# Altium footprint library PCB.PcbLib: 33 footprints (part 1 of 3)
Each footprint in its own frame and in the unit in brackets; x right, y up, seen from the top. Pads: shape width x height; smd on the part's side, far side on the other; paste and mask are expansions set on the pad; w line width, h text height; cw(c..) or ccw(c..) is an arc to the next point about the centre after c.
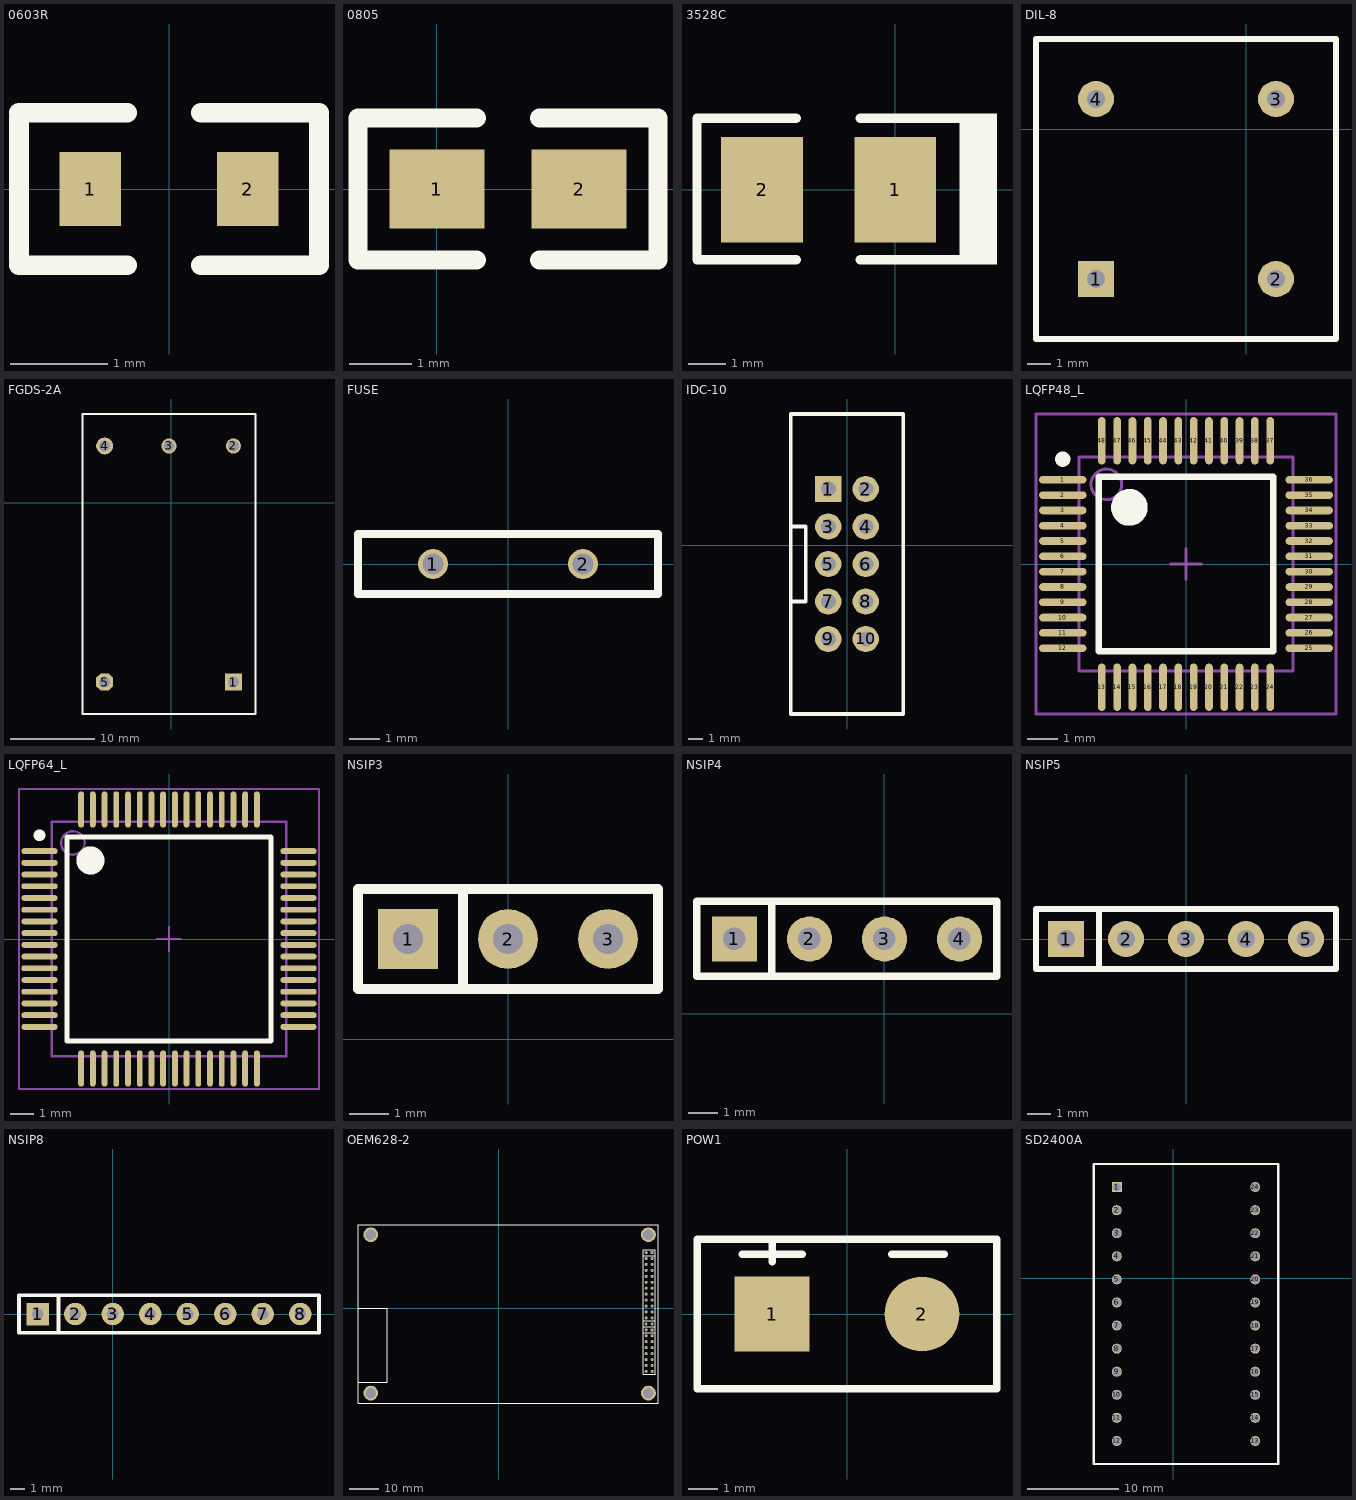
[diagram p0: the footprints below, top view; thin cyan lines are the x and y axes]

## 0603R [mil]
height 62.99
pads (2):
  rect 25x30 smd: 1(-32,0) 2(32,0)
Top Overlay:
  lines w8: -61,-31 -17,-31 ; -61,-29 -61,29 ; -61,31 -17,31 ; 13,-31 61,-31 ; 13,31 61,31 ; 61,-29 61,29

## 0805 [mil]
pads (2):
  rect 60x50 smd: 1(0,0) 2(90,0)
Top Overlay:
  lines w12: 25,-45 -50,-45 -50,45 25,45 ; 65,-45 140,-45 140,45 65,45

## 3528C [mm]
pads (2):
  rect 2.2x2.85 smd: 1(0,0) 2(-3.581,0)
Top Overlay:
  rectangle: 1.727,-2.014 2.743,2.058
  lines w0.254: -2.667,-1.88 -5.334,-1.88 -5.334,1.93 -2.667,1.93 ; -0.94,-1.88 1.727,-1.88 ; -0.94,1.93 1.727,1.93

## DIL-8 [mil]
pads (4):
  rect 60x60 hole 30: 1(-250,-250)
  round 60 hole 30: 2(50,-250) 3(50,50) 4(-250,50)
Top Overlay:
  lines w10: -350,-350 150,-350 150,150 -350,150 -350,-350

## FGDS-2A [mm]
height 1.6
pads (5):
  rect 2x2 hole 1.3: 1(7.37,-21.22)
  round 1.8 hole 1.3: 2(7.37,6.72) 3(-0.25,6.72)
  round 2 hole 1.3: 4(-7.87,6.72)
  oct 2x2 hole 1.3: 5(-7.87,-21.22)
Top Overlay:
  lines w0.254: -10.5,-25 -10.5,10.5 10,10.5 10,-25 -10.5,-25

## FUSE [mm]
height 1.6
pads (2):
  round 1 hole 0.7: 1(-2.5,0) 2(2.5,0)
Top Overlay:
  lines w0.254: -5,-1 5,-1 5,1 -5,1 -5,-1

## IDC-10 [mil] "XZZ"
pads (10):
  rect 70x70 hole 40: 1(-50,150)
  round 70 hole 40: 2(50,150) 3(-50,50) 4(50,50) 5(-50,-50) 6(50,-50) 7(-50,-150) 8(50,-150) 9(-50,-250) 10(50,-250)
Top Overlay:
  lines w10: -150,-150 -110,-150 -110,50 -150,50 ; -150,-450 -150,350 150,350 150,-450 -150,-450

## LQFP48_L [mm]
height 1.6
pads (48):
  oval 1.55x0.25 smd: 1(-4.025,2.75) 2(-4.025,2.25) 3(-4.025,1.75) 4(-4.025,1.25) 5(-4.025,0.75) 6(-4.025,0.25) 7(-4.025,-0.25) 8(-4.025,-0.75) 9(-4.025,-1.25) 10(-4.025,-1.75) 11(-4.025,-2.25) 12(-4.025,-2.75) 25(4.025,-2.75) 26(4.025,-2.25) 27(4.025,-1.75) 28(4.025,-1.25) 29(4.025,-0.75) 30(4.025,-0.25) 31(4.025,0.25) 32(4.025,0.75) 33(4.025,1.25) 34(4.025,1.75) 35(4.025,2.25) 36(4.025,2.75)
  oval 0.25x1.55 smd: 13(-2.75,-4.025) 14(-2.25,-4.025) 15(-1.75,-4.025) 16(-1.25,-4.025) 17(-0.75,-4.025) 18(-0.25,-4.025) 19(0.25,-4.025) 20(0.75,-4.025) 21(1.25,-4.025) 22(1.75,-4.025) 23(2.25,-4.025) 24(2.75,-4.025) 37(2.75,4.025) 38(2.25,4.025) 39(1.75,4.025) 40(1.25,4.025) 41(0.75,4.025) 42(0.25,4.025) 43(-0.25,4.025) 44(-0.75,4.025) 45(-1.25,4.025) 46(-1.75,4.025) 47(-2.25,4.025) 48(-2.75,4.025)
Top Overlay:
  circle w0.25: c-4.025,3.425 r0.125
  circle w0.6: c-1.85,1.85 r0.3
  lines w0.2: -2.85,-2.85 -2.85,2.85 2.85,2.85 2.85,-2.85 -2.85,-2.85
Mechanical 13:
  circle w0.1: c-2.6,2.6 r0.5
  lines w0.1: -3.5,-3.5 -3.5,3.5 3.5,3.5 3.5,-3.5 -3.5,-3.5
Mechanical 15:
  lines w0.1: -0.5,0 0.5,0 ; 0,-0.5 0,0.5 ; -4.9,-4.9 -4.9,4.9 4.9,4.9 4.9,-4.9 -4.9,-4.9

## LQFP64_L [mm]
pads (64):
  oval 1.55x0.25 smd: 1(-5.525,3.75) 2(-5.525,3.25) 3(-5.525,2.75) 4(-5.525,2.25) 5(-5.525,1.75) 6(-5.525,1.25) 7(-5.525,0.75) 8(-5.525,0.25) 9(-5.525,-0.25) 10(-5.525,-0.75) 11(-5.525,-1.25) 12(-5.525,-1.75) 13(-5.525,-2.25) 14(-5.525,-2.75) 15(-5.525,-3.25) 16(-5.525,-3.75) 33(5.525,-3.75) 34(5.525,-3.25) 35(5.525,-2.75) 36(5.525,-2.25) 37(5.525,-1.75) 38(5.525,-1.25) 39(5.525,-0.75) 40(5.525,-0.25) 41(5.525,0.25) 42(5.525,0.75) 43(5.525,1.25) 44(5.525,1.75) 45(5.525,2.25) 46(5.525,2.75) 47(5.525,3.25) 48(5.525,3.75)
  oval 0.25x1.55 smd: 17(-3.75,-5.525) 18(-3.25,-5.525) 19(-2.75,-5.525) 20(-2.25,-5.525) 21(-1.75,-5.525) 22(-1.25,-5.525) 23(-0.75,-5.525) 24(-0.25,-5.525) 25(0.25,-5.525) 26(0.75,-5.525) 27(1.25,-5.525) 28(1.75,-5.525) 29(2.25,-5.525) 30(2.75,-5.525) 31(3.25,-5.525) 32(3.75,-5.525) 49(3.75,5.525) 50(3.25,5.525) 51(2.75,5.525) 52(2.25,5.525) 53(1.75,5.525) 54(1.25,5.525) 55(0.75,5.525) 56(0.25,5.525) 57(-0.25,5.525) 58(-0.75,5.525) 59(-1.25,5.525) 60(-1.75,5.525) 61(-2.25,5.525) 62(-2.75,5.525) 63(-3.25,5.525) 64(-3.75,5.525)
Top Overlay:
  circle w0.25: c-5.525,4.425 r0.125
  circle w0.6: c-3.35,3.35 r0.3
  lines w0.2: -4.35,-4.35 -4.35,4.35 4.35,4.35 4.35,-4.35 -4.35,-4.35
Mechanical 13:
  circle w0.1: c-4.1,4.1 r0.5
  lines w0.1: -5,-5 -5,5 5,5 5,-5 -5,-5
Mechanical 15:
  lines w0.1: -0.5,0 0.5,0 ; 0,-0.5 0,0.5 ; -6.4,-6.4 -6.4,6.4 6.4,6.4 6.4,-6.4 -6.4,-6.4

## NSIP3 [mil]
height 62.99
pads (3):
  rect 60x60 hole 30: 1(-100,100)
  round 60 hole 30: 2(0,100) 3(100,100)
Top Overlay:
  lines w10: -45,50 -45,150 ; -150,50 -150,150 150,150 150,50 -150,50

## NSIP4 [mil]
height 62.99
pads (4):
  rect 60x60 hole 30: 1(-200,100)
  round 60 hole 30: 2(-100,100) 3(0,100) 4(100,100)
Top Overlay:
  lines w10: -150,50 -150,150 ; -250,50 -250,150 150,150 150,50 -250,50

## NSIP5 [mil]
height 62.99
pads (5):
  rect 60x60 hole 30: 1(-200,0)
  round 60 hole 30: 2(-100,0) 3(0,0) 4(100,0) 5(200,0)
Top Overlay:
  lines w10: -145,-50 -145,50 ; -250,-50 -250,50 250,50 250,-50 -250,-50

## NSIP8 [mil]
pads (8):
  rect 60x60 hole 30: 1(-200,0)
  round 60 hole 30: 2(-100,0) 3(0,0) 4(100,0) 5(200,0) 6(300,0) 7(400,0) 8(500,0)
Top Overlay:
  lines w10: -145,-50 -145,50 ; -250,-50 550,-50 550,50 -250,50 -250,-50

## OEM628-2 [mil]
pads (46):
  rect 40x40 hole 25: 1(2033.07,735.43) 27(2033.07,-288.19)
  round 40 hole 25: 2(1954.33,735.43) 3(2033.07,656.69) 4(1954.33,656.69) 5(2033.07,577.95) 6(1954.33,577.95) 7(2033.07,499.21) 8(1954.33,499.21) 9(2033.07,420.47) 10(1954.33,420.47) 11(2033.07,341.73) 12(1954.33,341.73) 13(2033.07,262.99) 14(1954.33,262.99) 15(2033.07,184.25) 16(1954.33,184.25) 17(2033.07,105.51) 18(1954.33,105.51) 19(2033.07,26.77) 20(1954.33,26.77) 21(2033.07,-51.97) 22(1954.33,-51.97) 23(2033.07,-130.71) 24(1954.33,-130.71) 28(1954.33,-288.19) 29(2033.07,-366.93) 30(1954.33,-366.93) 31(2033.07,-445.67) 32(1954.33,-445.67) 33(2033.07,-524.41) 34(1954.33,-524.41) 35(2033.07,-603.15) 36(1954.33,-603.15) 37(2033.07,-681.89) 38(1954.33,-681.89) 39(2033.07,-760.63) 40(1954.33,-760.63) 41(2033.07,-839.37) 42(1954.33,-839.37)
  oct 40x40 hole 25: 25(2033.07,-209.45) 26(1954.33,-209.45)
  round 196.85 hole 137.8: ""(-1696.85,-1127.56) ""(-1696.85,972.44) ""(1983.07,-1127.56) ""(1983.07,972.44)
Top Overlay:
  lines w10: -1866.14,-984.25 -1476.38,-984.25 -1476.38,0 -1866.14,0 ; 1914.96,-327.56 2072.44,-327.56 ; 1914.96,-248.82 2072.44,-248.82 ; 1914.96,-170.08 2072.44,-170.08 ; 1914.96,696.06 2072.44,696.06 ; -1866.14,-1259.84 -1866.14,1102.36 2110.24,1102.36 2110.24,-1259.84 -1866.14,-1259.84 ; 1914.96,-878.74 2072.44,-878.74 2072.44,774.8 1914.96,774.8 1914.96,-878.74

## POW1 [mm]
pads (2):
  rect 2.54x2.54 smd: 1(-2.54,0)
  round 2.54 smd: 2(2.54,0)
Top Overlay:
  lines w0.254: -3.556,2.032 -1.524,2.032 ; -2.54,1.778 -2.54,2.54 ; 1.524,2.032 3.302,2.032 ; -5.08,-2.54 -5.08,2.54 5.08,2.54 5.08,-2.54 -5.08,-2.54

## SD2400A [mm]
pads (24):
  rect 1.1x1.1 hole 0.9: 1(-6.223,10.033)
  round 1.1 hole 0.9: 2(-6.223,7.493) 3(-6.223,4.953) 4(-6.223,2.413) 5(-6.223,-0.127) 6(-6.223,-2.667) 7(-6.223,-5.207) 8(-6.223,-7.747) 9(-6.223,-10.287) 10(-6.223,-12.827) 11(-6.223,-15.367) 12(-6.223,-17.907) 13(9.017,-17.907) 14(9.017,-15.367) 15(9.017,-12.827) 16(9.017,-10.287) 17(9.017,-7.747) 18(9.017,-5.207) 19(9.017,-2.667) 20(9.017,-0.127) 21(9.017,2.413) 22(9.017,4.953) 23(9.017,7.493) 24(9.017,10.033)
Top Overlay:
  lines w0.254: -8.763,-20.447 -8.763,12.573 11.557,12.573 11.557,-20.447 -8.763,-20.447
